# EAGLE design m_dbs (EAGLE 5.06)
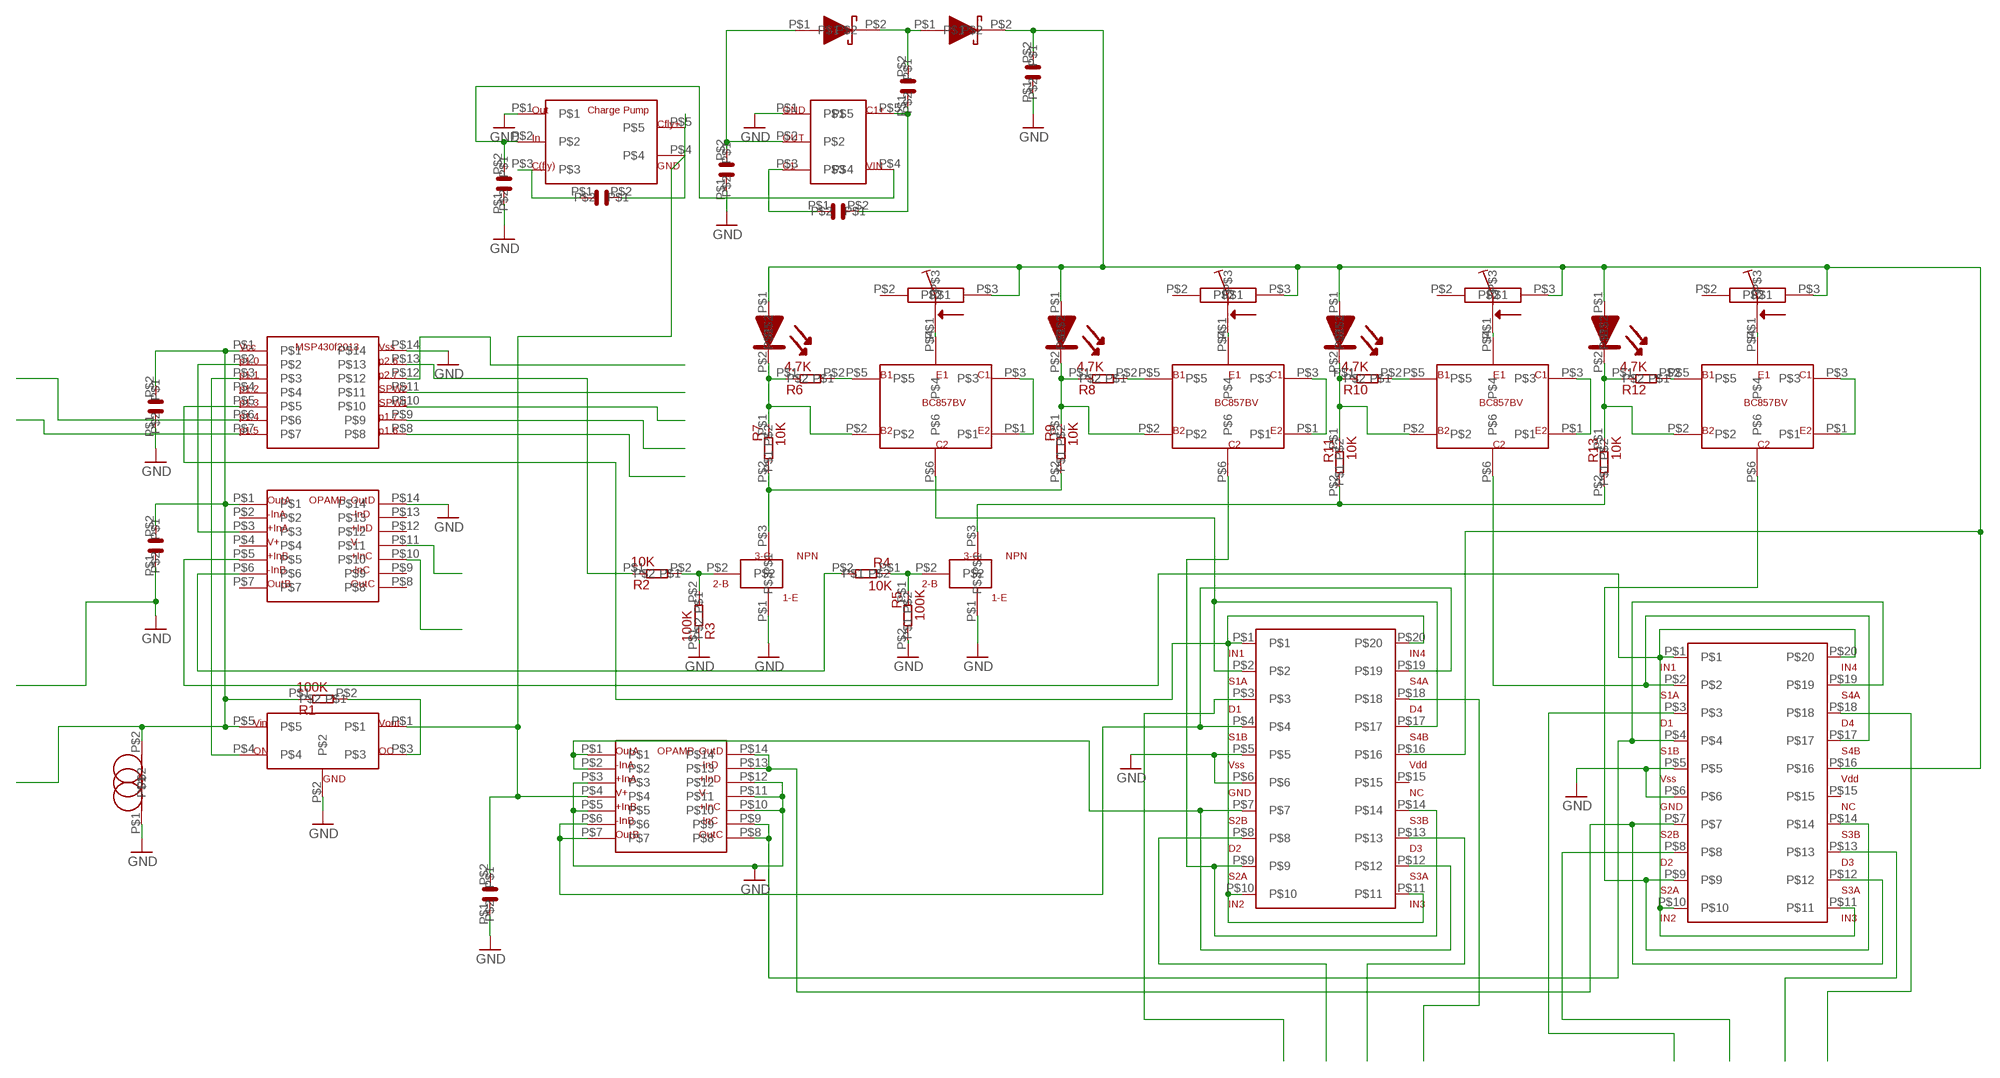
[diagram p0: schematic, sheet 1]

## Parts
C1  1uF  CAP0402  [0402]
C2  1uF  CAP0402  [0402]
C3  1uF  CAP0402  [0402]
C4  10uF  IND0603  [0603]
C5  1uF  CAP0402  [0402]
C6  1uF  CAP0402  [0402]
C7  1uF  CAP0402  [0402]
C8  1uF  CAP0402  [0402]
C9  1uF  CAP0402  [0402]
C10  1uF  CAP0402  [0402]
CP1  CHARGEPUMP  [SOT-23]
CP2  MAX1683  [SOT-23]
D1  DIODE  [SOD923-MC]
D2  DIODE  [SOD923-MC]
LED1  LED  [0402]
LED2  LED  [0402]
LED3  LED  [0402]
LED4  LED  [0402]
MCU1  MSP430F2013  [TSSOP-14]
MCU2  OPAMP  [TSSOP-14]
NPN1  NPN  [SOT-523]
NPN2  NPN  [SOT-523]
OPAMP  OPAMP  [TSSOP-14]
PNP1  BC857BV  [SOT-666]
PNP2  BC857BV  [SOT-666]
PNP3  BC857BV  [SOT-666]
PNP4  BC857BV  [SOT-666]
R1  100K  RES0402  [0402]
R2  10K  RES0402  [0402]
R3  100K  RES0402  [0402]
R4  10K  RES0402  [0402]
R5  100K  RES0402  [0402]
R6  4.7K  RES0402  [0402]
R7  10K  RES0402  [0402]
R8  4.7K  RES0402  [0402]
R9  10K  RES0402  [0402]
R10  4.7K  RES0402  [0402]
R11  10K  RES0402  [0402]
R12  4.7K  RES0402  [0402]
R13  10K  RES0402  [0402]
SPDT1  ADG333  [SSOP-20]
SPDT2  ADG333  [SSOP-20]
SWITCH  SWITCH  [SC70-5]
T1  50K  TRIMMER2MM  [TRIM-MC]
T2  50K  TRIMMER2MM  [TRIM-MC]
T3  50K  TRIMMER2MM  [TRIM-MC]
T4  50K  TRIMMER2MM  [TRIM-MC]

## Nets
GND: C1.P$1 C2.P$1 C3.P$1 C4.P$1 C5.P$1 C7.P$1 C10.P$1 CP1.P$1 CP2.P$1 MCU1.P$14 MCU2.P$14 NPN1.P$1 NPN2.P$1 OPAMP.P$3 OPAMP.P$5 OPAMP.P$10 OPAMP.P$11 OPAMP.P$12 R3.P$1 R5.P$2 SPDT1.P$5 SPDT1.P$6 SPDT2.P$5 SPDT2.P$6 SWITCH.P$2
N$1: LED1.P$2 PNP1.P$2 R6.P$1 R7.P$1
N$2: PNP1.P$5 R6.P$2
N$3: LED2.P$2 PNP2.P$2 R8.P$1 R9.P$1
N$4: PNP2.P$5 R8.P$2
N$5: LED3.P$2 PNP3.P$2 R10.P$1 R11.P$1
N$6: PNP3.P$5 R10.P$2
N$7: LED4.P$2 PNP4.P$2 R12.P$1 R13.P$1
N$8: PNP4.P$5 R12.P$2
N$9: PNP1.P$4 T1.P$1
N$10: PNP2.P$4 T2.P$1
N$11: PNP3.P$4 T3.P$1
N$12: PNP4.P$4 T4.P$1
N$13: OPAMP.P$1 OPAMP.P$2 SPDT1.P$7 SPDT1.P$12
N$14: NPN1.P$3 R7.P$2 R9.P$2
N$15: NPN2.P$2 R4.P$1 R5.P$1
N$16: MCU2.P$6 R4.P$2
N$17: MCU1.P$2 MCU2.P$3
N$18: PNP1.P$1 PNP1.P$3
N$19: PNP2.P$1 PNP2.P$3
N$20: PNP3.P$1 PNP3.P$3
N$21: PNP4.P$1 PNP4.P$3
N$22: NPN1.P$2 R2.P$2 R3.P$2
N$23: MCU1.P$13 R2.P$1
N$24: NPN2.P$3 R11.P$2 R13.P$2
N$25: MCU1.P$3 SWITCH.P$4
N$26: R1.P$2 SWITCH.P$3
N$27: C1.P$2 C2.P$2 C4.P$2 MCU1.P$1 MCU2.P$1 R1.P$1 SWITCH.P$5
N$28: MCU1.P$5 SPDT1.P$1 SPDT1.P$10 SPDT1.P$11 SPDT1.P$20
N$29: MCU2.P$5 SPDT2.P$1 SPDT2.P$10 SPDT2.P$11 SPDT2.P$20
N$30: C3.P$2 CP1.P$4 OPAMP.P$4 SWITCH.P$1
N$33: OPAMP.P$8 OPAMP.P$9 SPDT2.P$4 SPDT2.P$19
N$34: OPAMP.P$13 OPAMP.P$14 SPDT2.P$7 SPDT2.P$12
N$35: C8.P$1 CP2.P$3
N$36: C6.P$1 CP1.P$3
N$37: C6.P$2 CP1.P$5
N$38: C5.P$2 CP1.P$2 CP2.P$4
N$39: C8.P$2 C9.P$1 CP2.P$5
N$40: C9.P$2 D1.P$2 D2.P$1
N$41: C10.P$2 D2.P$2 LED1.P$1 LED2.P$1 LED3.P$1 LED4.P$1 SPDT1.P$16 SPDT2.P$16 T1.P$3 T2.P$3 T3.P$3 T4.P$3
N$42: C7.P$2 CP2.P$2 D1.P$1
N$43: OPAMP.P$6 OPAMP.P$7 SPDT1.P$4 SPDT1.P$19
N$44: PNP1.P$6 SPDT1.P$2 SPDT1.P$17
N$51: PNP3.P$6 SPDT2.P$2 SPDT2.P$17
N$53: PNP4.P$6 SPDT2.P$9 SPDT2.P$14
N$59: MCU1.P$6
N$60: PNP2.P$6 SPDT1.P$9 SPDT1.P$14
N$67: MCU1.P$7
N$68: MCU1.P$11
N$69: MCU1.P$10
N$70: MCU1.P$9
N$71: MCU1.P$8
N$72: MCU1.P$12
N$73: SPDT2.P$8
N$74: MCU2.P$11
N$75: MCU2.P$10
N$76: SPDT1.P$3
N$77: SPDT1.P$8
N$78: SPDT1.P$13
N$79: SPDT1.P$18
N$80: SPDT2.P$3
N$81: SPDT2.P$13
N$82: SPDT2.P$18
Unconnected: MCU1.P$4 MCU2.P$2 MCU2.P$4 MCU2.P$7 MCU2.P$8 MCU2.P$9 MCU2.P$12 MCU2.P$13 SPDT1.P$15 SPDT2.P$15 T1.P$2 T2.P$2 T3.P$2 T4.P$2

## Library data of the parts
C1-C3 C5-C10 = my project parts:CAP0402
C4 = my project parts:IND0603
CP1 = my project parts:CHARGEPUMP
CP2 = my project parts:MAX1683
D1 D2 = my project parts:DIODE
LED1-LED4 = my project parts:LED
MCU1 = my project parts:MSP430F2013
MCU2 OPAMP = my project parts:OPAMP
NPN1 NPN2 = my project parts:NPN
PNP1-PNP4 = my project parts:BC857BV
R1-R13 = my project parts:RES0402
SPDT1 SPDT2 = my project parts:ADG333
SWITCH = my project parts:SWITCH
T1-T4 = my project parts:TRIMMER2MM

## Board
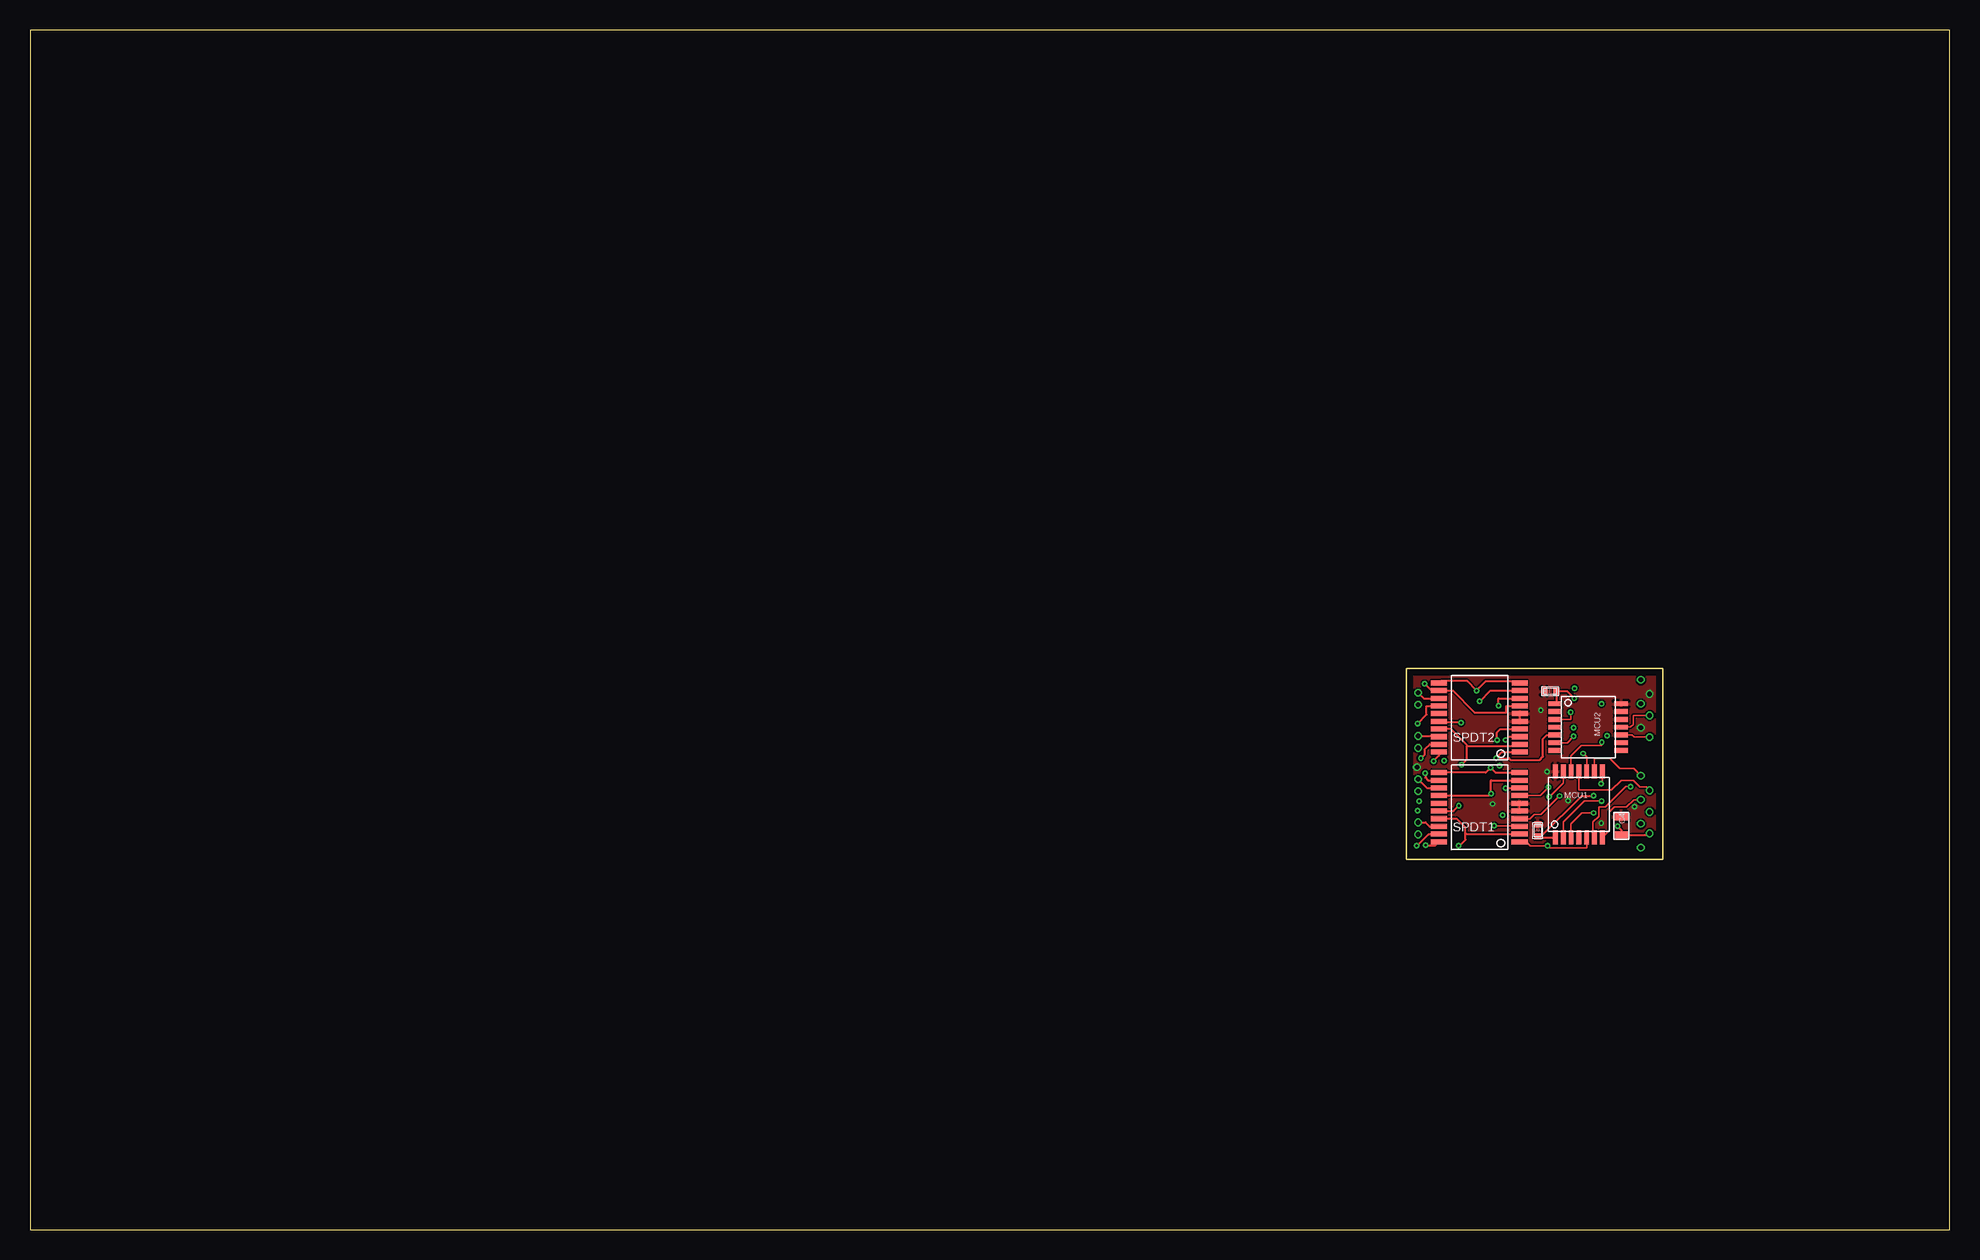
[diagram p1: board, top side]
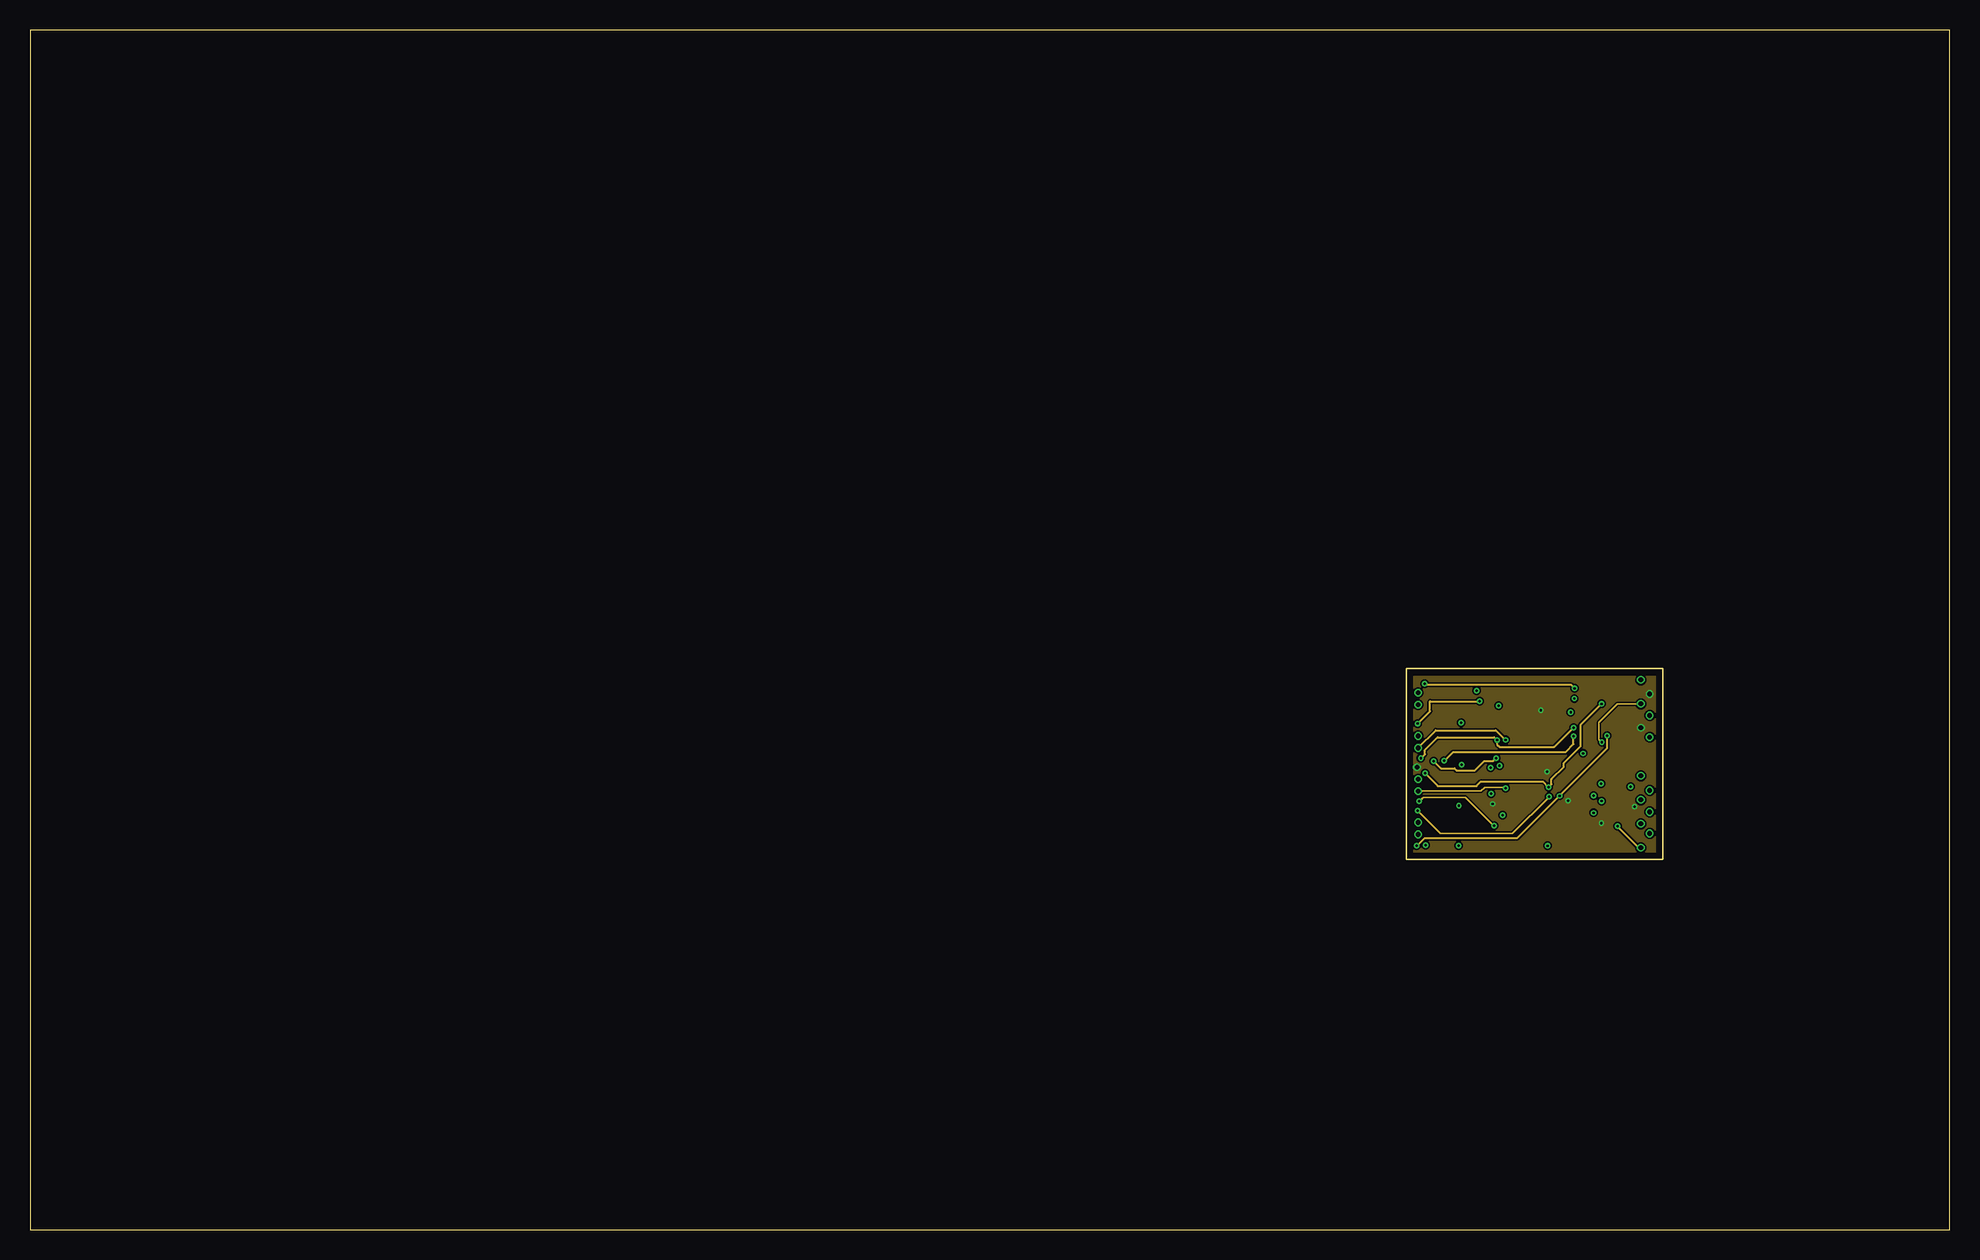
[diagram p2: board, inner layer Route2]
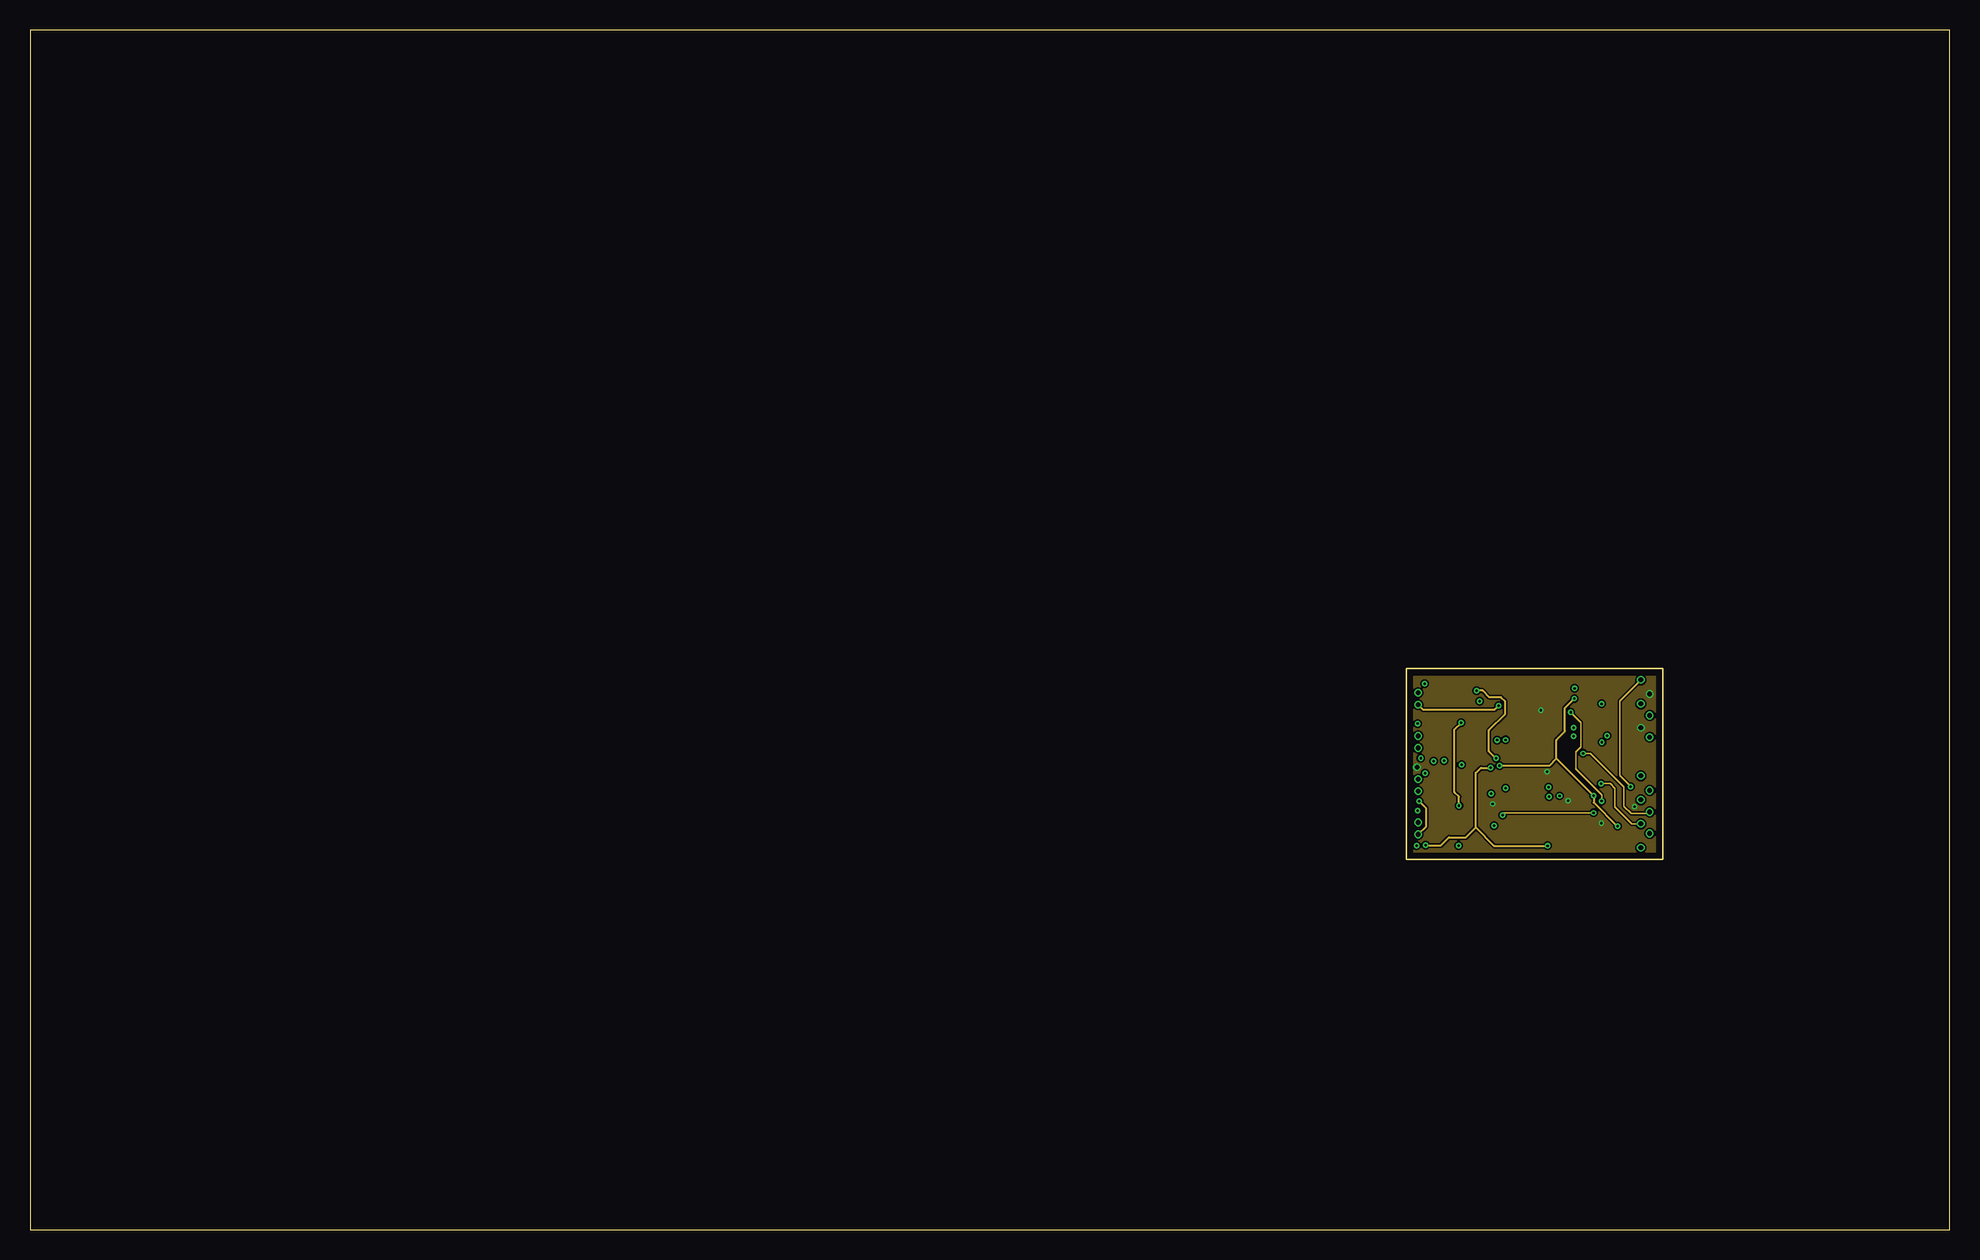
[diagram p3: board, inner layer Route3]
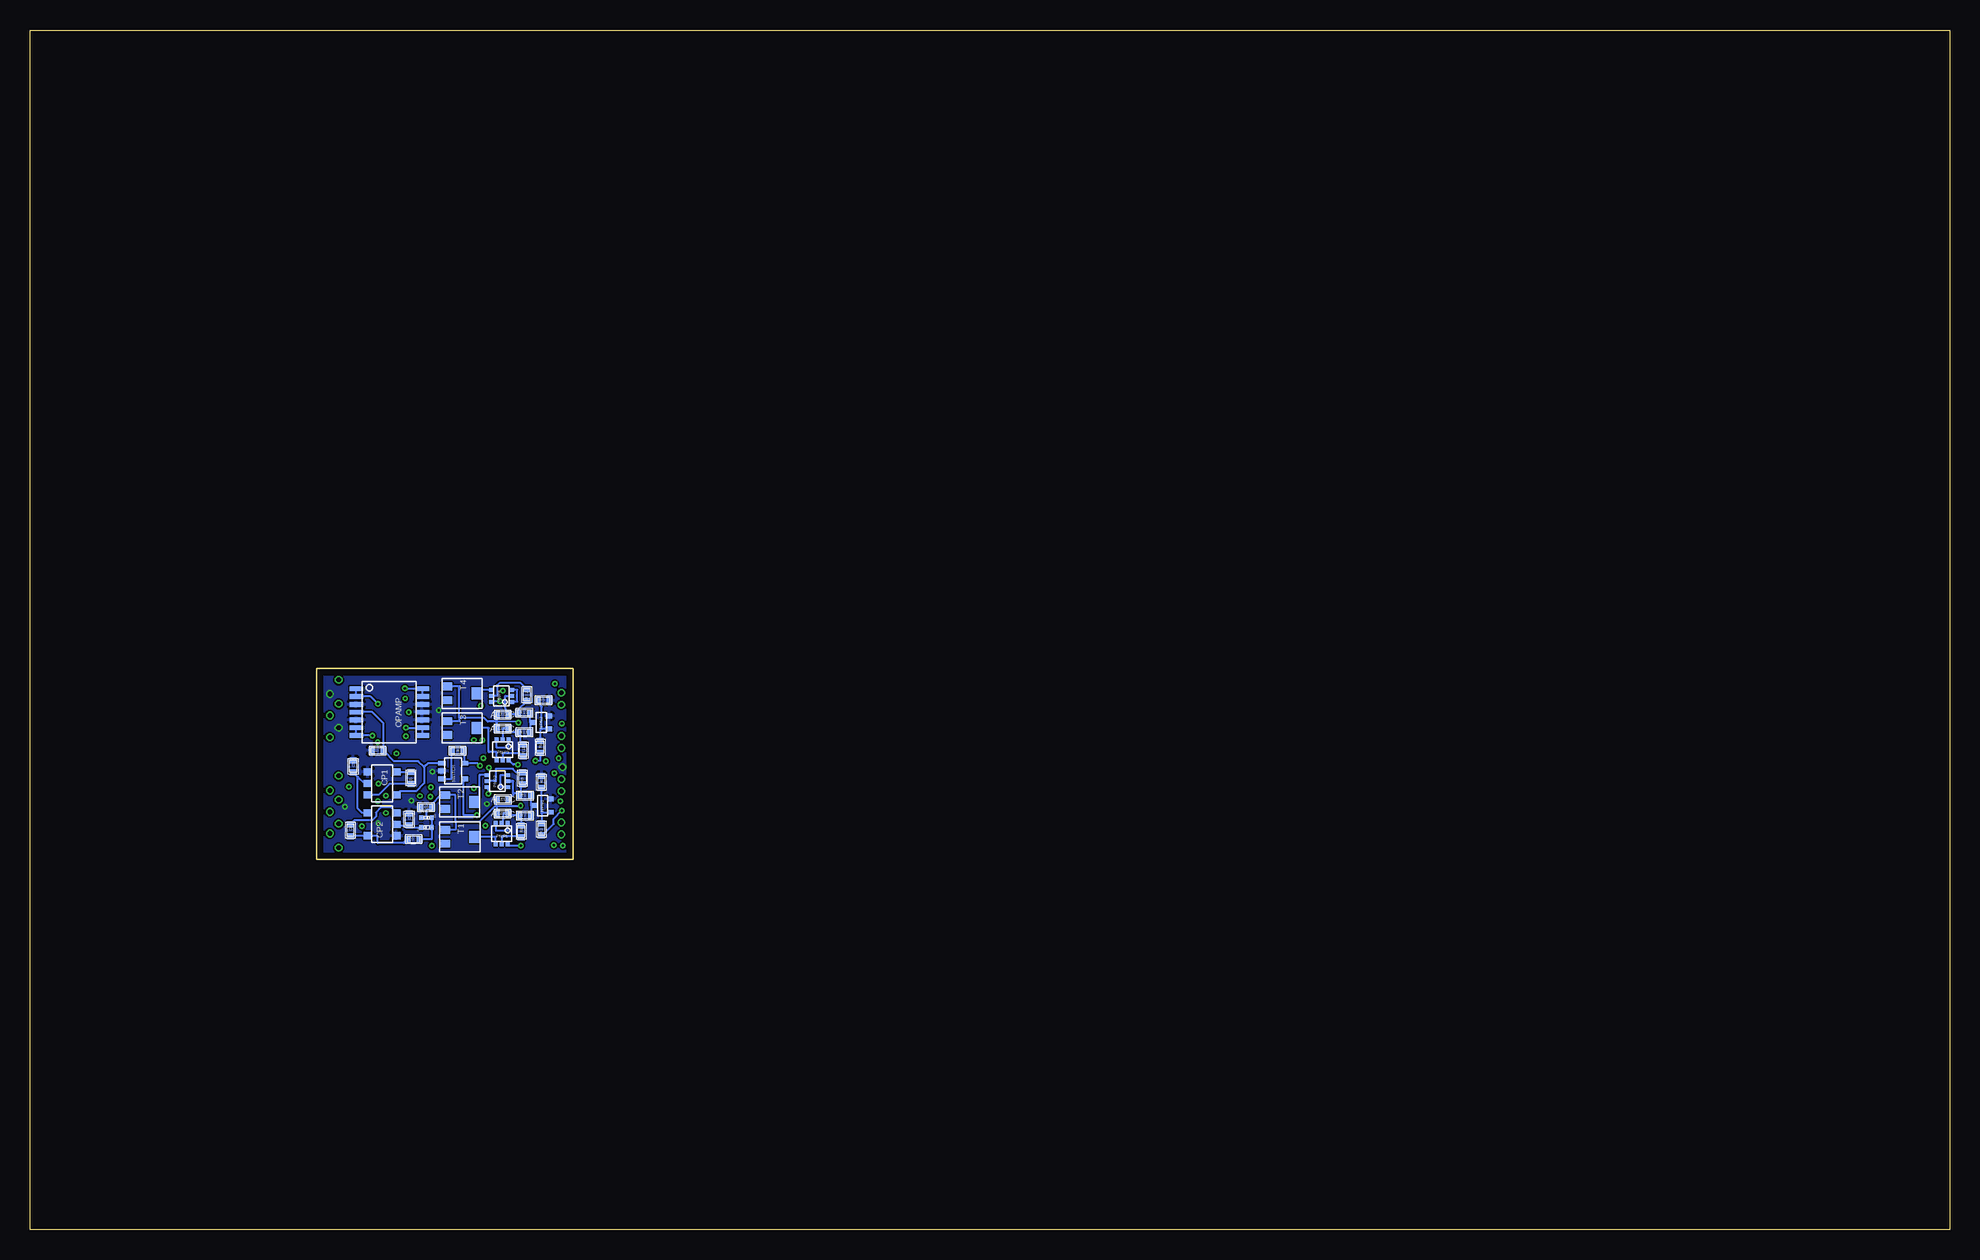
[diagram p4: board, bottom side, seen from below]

Size 160 x 100 mm. Coordinates in mm from the lower left corner, seen from the top.
Outline: 0,0 160,0 160,100 0,100 0,0
Outline: 114.72,46.78 136.1,46.78 136.1,30.85 114.72,30.85 114.72,46.78
Copper layers (1+2*3+16): Top 0.035mm / dielectric 0.38mm / Route2 0.035mm / dielectric 0.71mm / Route3 0.035mm / dielectric 0.38mm / Bottom 0.035mm
Design rules "default *": minimum track width 0.125mm, minimum drill 0.2mm, track to track 5mil, track to pad 6mil, pad to pad 6mil, via to via 5mil, smd to smd 6mil, copper to edge 0.5mm, drill to drill 8mil, minimum pad ring 10mil, minimum via ring 5mil, stop-mask expansion 3mil, vias tented up to drill 8mil, thermal gap 0.2mm

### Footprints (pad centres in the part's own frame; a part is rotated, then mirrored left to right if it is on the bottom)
0402 = smd 0.5 x 0.6: P$1 -0.5,0; P$2 0.5,0
0603 = smd 0.629 x 1.138: P$1 -0.764,0; P$2 0.764,0
SOT-23 = smd 0.6 x 0.725: P$1 -0.95,-1.188; P$2 0,-1.188; P$3 0.95,-1.188; P$4 0.95,1.188; P$5 -0.95,1.188
SOD923-MC = smd 0.3 x 0.4: P$1 -0.45,0; P$2 0.45,0
TSSOP-14 = smd 0.4 x 1.15: P$1 -1.95,-2.75; P$2 -1.3,-2.75; P$3 -0.65,-2.75; P$4 0,-2.75; P$5 0.65,-2.75; P$6 1.3,-2.75; P$7 1.95,-2.75; P$8 1.95,2.75; P$9 1.3,2.75; P$10 0.65,2.75; P$11 0,2.75; P$12 -0.65,2.75; P$13 -1.3,2.75; P$14 -1.95,2.75
SOT-523 = smd 0.4 x 0.55: P$1 0.55,-0.65; P$2 -0.55,-0.65; P$3 0,0.65
SOT-666 = smd 0.3 x 0.4: P$1 -0.5,-0.85; P$2 0,-0.85; P$3 0.5,-0.85; P$4 0.5,0.85; P$5 0,0.85; P$6 -0.5,0.85
SSOP-20 = smd 0.42 x 1.34: P$1 -2.88,-3.36; P$2 -2.24,-3.36; P$3 -1.6,-3.36; P$4 -0.96,-3.36; P$5 -0.32,-3.36; P$6 0.32,-3.36; P$7 0.96,-3.36; P$8 1.6,-3.36; P$9 2.24,-3.36; P$10 2.88,-3.36; P$11 2.88,3.36; P$12 2.24,3.36; P$13 1.6,3.36; P$14 0.96,3.36; P$15 0.32,3.36; P$16 -0.32,3.36; P$17 -0.96,3.36; P$18 -1.6,3.36; P$19 -2.24,3.36; P$20 -2.88,3.36
SC70-5 = smd 0.4 x 0.6: P$1 -0.65,-0.95; P$2 0,-0.95; P$3 0.65,-0.95; P$4 0.65,0.95; P$5 -0.65,0.95
TRIM-MC = smd 1 x 0.9: P$1 0,1.25 | smd 0.65 x 0.9: P$2 0.575,-1.25; P$3 -0.575,-1.25

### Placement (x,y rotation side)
C1  126.71,44.87 0 top
C2  125.68,33.25 270 top
C3  131.03,39.92 0 bottom
C4  132.64,33.65 270 top
C5  133.06,38.61 270 bottom
C6  128.24,37.65 90 bottom
C7  128.39,34.2 270 bottom
C8  133.29,33.29 270 bottom
C9  128.02,32.53 0 bottom
C10  127,35.2 0 bottom
CP1  130.65,37.19 270 bottom
CP2  130.65,33.78 90 bottom
D1  126.94,33.52 0 bottom
D2  126.94,34.33 180 bottom
LED1  120.61,34.67 0 bottom
LED2  120.59,35.85 0 bottom
LED3  120.6,41.75 0 bottom
LED4  120.6,42.92 0 bottom
MCU1  129.11,35.45 0 top
MCU2  129.88,41.88 270 top
NPN1  117.27,35.35 90 bottom
NPN2  117.39,42.27 90 bottom
OPAMP  130.04,43.13 270 bottom
PNP1  120.69,33 180 bottom
PNP2  121.04,37.38 90 bottom
PNP3  120.61,39.99 180 bottom
PNP4  120.7,44.48 90 bottom
R1  124.37,39.92 180 bottom
R2  117.37,33.36 90 bottom
R3  117.37,37.3 270 bottom
R4  117.47,40.21 270 bottom
R5  117.2,44.12 0 bottom
R6  119.05,33.18 270 bottom
R7  118.74,34.51 0 bottom
R8  118.94,37.62 90 bottom
R9  118.74,36.18 0 bottom
R10  118.89,39.95 270 bottom
R11  118.8,41.44 0 bottom
R12  118.58,44.57 90 bottom
R13  118.8,43.07 0 bottom
SPDT1  120.81,35.21 90 top
SPDT2  120.81,42.68 90 top
SWITCH  124.72,38.22 270 bottom
T1  124.19,32.74 270 bottom
T2  124.19,35.63 270 bottom
T3  124,41.8 270 bottom
T4  124,44.7 270 bottom

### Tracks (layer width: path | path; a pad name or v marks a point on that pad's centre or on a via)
GND  (via drill 0.2, 0.4)
  Top 0.125: SPDT2.P$6 SPDT2.P$5 | SPDT1.P$6 SPDT1.P$5
  other vias: 130.98,33.86 128.21,35.76 134.28,41.83 135,44.64 125.94,43.28 126.47,38.16 115.62,38.55 133.75,35.26 121.92,35.48
  pour Top: 114.83,46.27 135.74,46.27 135.74,31.24 114.83,31.24 114.83,46.27
  pour Route2: 114.84,46.27 135.75,46.27 135.75,31.18 114.84,31.18 114.84,46.27
  pour Route3: 114.83,46.28 135.75,46.28 135.75,31.21 114.83,31.21 114.83,46.28
  pour Bottom: 114.88,46.22 135.77,46.22 135.77,31.21 114.88,31.21
N$1
  Bottom 0.125: LED1.P$2 120.11,34.51 | R7.P$1 119.05,34.51 119.05,34.5 | R6.P$1 119.05,33.5
  Bottom 0.15: PNP1.P$2 arc-27 120.56,34.37 120.56,34.67 LED1.P$2 119.94,34.51 R7.P$1 | 119.05,34.5 R6.P$1
N$2
  Bottom 0.125: 118.97,32.66 R6.P$2 119.11,32.66
  Bottom 0.15: PNP1.P$5 120.69,32.79 119.05,32.79 R6.P$2
N$3
  Bottom 0.125: R8.P$1 119.15,37.23 | R9.P$1 119.05,36.18 | R9.P$1 119.24,36.11 | PNP2.P$2 arc-90 120.1,37.29 119.72,37.29 | R9.P$1 119.24,36.37
  Bottom 0.15: 119.72,36.37 119.72,36.22 LED2.P$2 | 119.72,36.37 119.43,36.37 R9.P$1 | 119.72,36.37 119.72,37.38 PNP2.P$2 | 119.05,36.18 119.05,37.12 R8.P$1
N$4
  Bottom 0.125: 118.94,37.96 R8.P$2 118.94,38.2
  Bottom 0.15: PNP2.P$5 121.18,37.38 121.18,38.41 119.76,38.41 119.48,38.12 R8.P$2
N$5
  Bottom 0.125: 119.12,41.44 R11.P$1 | R10.P$1 119.12,40.45
  Bottom 0.15: PNP3.P$2 120.59,40.84 120.59,41.75 LED3.P$2 120.1,41.44 R11.P$1 | 119.12,41.44 119.12,40.67 R10.P$1
N$6
  Bottom 0.125: R10.P$2 118.89,39.62
  Bottom 0.15: PNP3.P$5 120.61,39.69 119.13,39.69 R10.P$2
N$7
  Bottom 0.125: 119.11,43.07 R13.P$1 119.3,42.92
  Bottom 0.15: 119.3,42.92 LED4.P$2 120.39,43.48 120.39,44.48 PNP4.P$2 | R12.P$1 119.3,43.35 R13.P$1
N$8
  Bottom 0.15: PNP4.P$5 121.06,44.48 121.06,45.36 120.87,45.55 119.09,45.55 118.61,45.07 R12.P$2
N$9
  Bottom 0.15: PNP1.P$4 121.19,32.74 T1.P$1
N$10
  Bottom 0.125: 122.55,36.02 T2.P$1
  Bottom 0.15: PNP2.P$4 122.55,37.88 122.55,36.02
N$11
  Bottom 0.15: PNP3.P$4 121.11,39.79 121.77,39.79 121.77,41.8 T3.P$1
N$12
  Bottom 0.125: PNP4.P$4 121.94,44.98
  Bottom 0.15: T4.P$1 122.75,44.98 PNP4.P$4
N$13  (via drill 0.2)
  Top 0.125: SPDT1.P$12 | v126.58,36.87 125.88,36.17 SPDT1.P$7
  Top 0.15: SPDT1.P$12 116.54,37.45 116.31,37.68 v116.31,38.05
  Route2 0.125: v116.31,38.05 116.31,38.01
  Route2 0.15: 116.31,38.01 117.35,36.96 120.56,36.96 120.95,37.35 126.1,37.35 v126.58,36.87 126.83,37.12 126.83,37.56 127.85,38.58 127.85,38.88 129.27,40.3 129.27,42.1 v130.98,43.81
  Bottom 0.15: OPAMP.P$1 OPAMP.P$2 131.6,44.43 v130.98,43.81
N$14
  Bottom 0.15: R9.P$2 118.24,35.35 NPN1.P$3 118.24,35.35 R7.P$2
N$15
  Bottom 0.125: 117.48,41.72 117.47,41.72 117.34,41.72
  Bottom 0.15: R4.P$1 117.47,41.72 NPN2.P$2 | 117.34,41.72 117.34,43.56 R5.P$1
N$16  (via drill 0.2)
  Top 0.125: MCU2.P$6 128.13,40.58 v128.66,41.12
  Route2 0.15: v117.89,39.07 118.63,39.81 128.01,39.81 128.66,40.47 v128.66,41.12
  Bottom 0.15: v117.89,39.07 117.47,39.07 R4.P$2
N$17  (via drill 0.2)
  Top 0.125: v131,35.73 129.54,35.73 127.81,33.99 MCU1.P$2 | MCU2.P$3 128.43,42.53 v128.43,43.11
  Route3 0.125: v131,35.73 131,36.24 128.86,38.39 128.86,39.82 129.26,40.22 129.26,42.29 v128.43,43.11
N$18
  Bottom 0.15: PNP1.P$1 120.19,33.25 121.19,33.25 PNP1.P$3
N$19
  Bottom 0.15: PNP2.P$3 120.78,37.88 120.78,36.88 PNP2.P$1
N$20
  Bottom 0.15: PNP3.P$1 120.11,40.2 121.11,40.2 PNP3.P$3
N$21
  Bottom 0.15: PNP4.P$3 119.38,44.98 119.38,43.98 PNP4.P$1
N$22
  Bottom 0.125: R3.P$2
  Bottom 0.15: 117.37,34.73 R2.P$2 | 117.37,34.73 R3.P$2 | NPN1.P$2 116.69,34.73 117.37,34.73
N$23  (via drill 0.2)
  Top 0.125: MCU1.P$13 127.81,37.24 v126.64,36.08
  Route2 0.125: v126.64,36.08 123.57,33 117.58,33 v115.66,34.92
  Bottom 0.15: R2.P$1 117.29,32.86 116.34,33.81 116.34,34.25 115.67,34.92 v115.66,34.92
N$24
  Bottom 0.125: 118.3,42.27 NPN2.P$3 118.3,42.27
  Bottom 0.15: 118.3,42.27 R11.P$2 | 118.3,42.27 R13.P$2
N$25  (via drill 0.2)
  Top 0.125: v130.35,34.73 129.37,34.73 128.46,33.82 MCU1.P$3
  Route3 0.125: v122.74,34.53 122.74,34.73 v130.35,34.73
  Bottom 0.125: 123.84,37.57 SWITCH.P$4 | 123.84,34.53
  Bottom 0.15: 123.84,37.57 123.84,34.53 v122.74,34.53
N$26
  Bottom 0.125: R1.P$2 124.95,39.84
  Bottom 0.15: SWITCH.P$3 124.87,37.57 R1.P$2
N$27  (via drill 0.2, 0.4)
  Top 0.125: 127.21,43.91 MCU2.P$1 | 125.74,32.7 C2.P$2 125.88,32.75 | C4.P$2 132.92,32.88
  Top 0.15: v128.73,44.27 128.13,44.87 C1.P$2 127.21,43.91 | v130.34,36.15 129.35,36.15 125.95,32.75 C2.P$2 | 125.74,32.7 MCU1.P$1 | v132.32,33.62 132.64,33.3 C4.P$2 134.87,32.88 v135,33.02
  Route2 0.15: v132.32,33.62 134.11,31.83 v134.28,31.83
  Route3 0.125: v132.32,33.62
  Route3 0.15: v128.73,44.27 127.96,43.5 127.96,41.53 127.24,40.81 127.24,39.25 | 127.24,39.25 126.64,38.66 v122.48,38.66 | 127.24,39.25 v130.34,36.15 130.34,35.6 v132.32,33.62
  Bottom 0.125: 123.77,39.81 R1.P$1
  Bottom 0.15: 123.77,39.81 SWITCH.P$5 122.7,38.87 v122.48,38.66
N$28  (via drill 0.2)
  Top 0.125: SPDT1.P$1 124.23,32.26 124.77,32.26 125.05,31.98 v126.5,31.98 126.69,31.8 129.76,31.8 MCU1.P$5
  Top 0.15: SPDT1.P$10 122.16,38.09 v121.75,38.5 121.35,38.09 SPDT1.P$11 | SPDT1.P$20 117.15,32.04 v116.34,32.04
  Route3 0.15: v116.34,32.04 117.62,32.04 118.29,32.7 119.7,32.7 120.5,33.5 | 120.5,33.5 122.03,31.98 v126.5,31.98 | 120.5,33.5 120.5,38.06 120.94,38.5 v121.75,38.5
N$29  (via drill 0.2)
  Top 0.125: 124.02,45.71 SPDT2.P$10 | 117.6,45.71 SPDT2.P$11
  Top 0.15: 124.02,45.71 121.36,45.71 v120.58,44.93 119.8,45.71 117.6,45.71 | v117,39.06 117.45,39.51 SPDT2.P$20 | SPDT2.P$1 122.71,39.8 v122.19,39.29 123.29,39.29 123.43,39.15 125.84,39.15 126.11,39.43 126.11,40.91 126.43,41.23 MCU2.P$5
  Route2 0.15: v117,39.06 117.62,38.44 118.74,38.44 118.9,38.28 120.45,38.28 121.22,39.05 121.95,39.05 v122.19,39.29
  Route3 0.15: v120.58,44.93 121.09,44.93 121.66,44.36 122.61,44.36 122.96,44.01 122.96,42.98 121.62,41.64 121.62,39.87 v122.19,39.29
N$30
  Bottom 0.125: 127.13,38.54 127.15,38.54
  Bottom 0.15: OPAMP.P$4 131.47,43.13 130.53,42.19 C3.P$2 129.64,39.03 127.64,39.03 127.15,38.54 | SWITCH.P$1 126.81,38.87 127.13,38.54 127.13,37.22 127.81,36.54 129.17,36.54 CP1.P$4
N$33  (via drill 0.2)
  Top 0.15: SPDT2.P$19 116.67,40.44 116.27,40.04 116.27,39.62 v115.94,39.29 | SPDT2.P$4 122.58,41.72 122.29,41.43 v122.29,40.81
  Route2 0.15: v115.94,39.29 116.27,39.62 116.27,39.98 117.33,41.04 122.06,41.04 v122.29,40.81 122.29,40.45 122.5,40.23 127.06,40.23 v128.66,41.83
  Bottom 0.15: OPAMP.P$8 OPAMP.P$9 v128.66,41.83
N$34  (via drill 0.2)
  Top 0.125: 116.82,44.92 SPDT2.P$12
  Top 0.15: SPDT2.P$7 123.05,43.64 123.05,43.09 120.42,43.09 118.59,44.92 SPDT2.P$12 | v116.25,45.49 116.82,44.92
  Route2 0.15: v116.25,45.49 116.31,45.43 128.43,45.43 v128.75,45.11
  Bottom 0.15: v128.75,45.11 127.32,45.11 OPAMP.P$14 OPAMP.P$13
N$35
  Bottom 0.15: CP2.P$3 129.9,35.17 130.75,35.17 131.15,34.77 131.15,34.42 131.46,34.11 132.97,34.11 C8.P$1
N$36
  Bottom 0.125: CP1.P$3 131.42,36.24 | C6.P$1 arc-90 C6.P$1
  Bottom 0.15: C6.P$1 130.03,37.16 130.95,36.24 CP1.P$3
N$37
  Bottom 0.125: C6.P$2
  Bottom 0.15: CP1.P$5 C6.P$2
N$38
  Bottom 0.125: CP1.P$2 131.84,37.13 132.08,37.13
  Bottom 0.15: 132.69,37.73 132.08,37.13 | 132.69,37.73 C5.P$2 | 132.69,37.73 132.69,35.09 132.33,34.73 CP2.P$4
N$39
  Bottom 0.125: 131.84,32.8 CP2.P$5 | C9.P$1 128.52,32.29
  Bottom 0.15: C8.P$2 131.84,32.8 131.01,32.8 131.01,32.22 128.83,32.22 C9.P$1
N$40
  Bottom 0.125: D2.P$1
  Bottom 0.15: C9.P$2 126.49,32.53 D1.P$2 D2.P$1
N$41  (via drill 0.2)
  Top 0.125: 117.56,42.25 SPDT2.P$16
  Top 0.15: v119.29,42.25 117.56,42.25 | SPDT1.P$16 118.66,34.89 v119.11,35.34
  Route3 0.125: 119.29,42.24 v119.29,42.25
  Route3 0.15: 119.29,42.24 118.75,41.69 118.75,36.45 119.11,36.09 v119.11,35.34
  Bottom 0.125: LED1.P$1 120.98,34.61 | LED1.P$1 121.11,34.74 | LED1.P$1 | LED4.P$1 121.1,42.34 119.38,42.34 v119.29,42.25 | 121.09,35.25 121.09,34.69 LED1.P$1 | T2.P$3 125.78,36.21
  Bottom 0.15: D2.P$2 126.99,34.33 126.99,34.98 126.5,34.98 C10.P$2 126.5,35.49 125.78,36.21 | T1.P$3 124.53,33.32 124.53,33.98 | T2.P$3 124.53,36.21 124.53,33.98 | 124.53,33.98 122.55,33.98 121.28,35.25 121.09,35.25 | 121.09,35.25 LED2.P$1 | 121.09,35.25 121.09,34.76 | 121.09,35.25 119.19,35.25 v119.11,35.34 | 124.22,42.63 122.13,42.63 121.84,42.34 121.1,42.34 LED3.P$1 | T3.P$3 124.22,42.37 124.22,42.63 | T4.P$3 124.22,45.27 124.22,42.63 | 121.1,42.99 121.1,41.64 LED4.P$1
N$42
  Bottom 0.125: CP2.P$2 129.46,33.7 | C7.P$2 128.39,33.52
  Bottom 0.15: 129.46,33.7 C7.P$2 128.21,33.52 D1.P$1
N$43  (via drill 0.2)
  Top 0.125: v115.6,32.01 115.6,32.11 115.76,32.11 | v127.49,36.15 125.95,34.6 125.39,34.6 125.04,34.25 SPDT1.P$4
  Top 0.15: SPDT1.P$19 116.6,32.97 115.65,32.01 v115.6,32.01
  Route2 0.125: v127.49,36.14 v127.49,36.15
  Route2 0.15: v131.47,41.17 131.47,40.13 v127.49,36.15 | v127.49,36.14 123.98,32.63 116.26,32.63 115.65,32.01 v115.6,32.01
  Bottom 0.15: OPAMP.P$6 OPAMP.P$7 131.48,41.18 v131.47,41.17
N$44  (via drill 0.2)
  Top 0.125: SPDT1.P$2 124.1,33.03
  Top 0.15: SPDT1.P$17 118.93,34.25 119.66,33.52 119.66,33.03 | 119.66,33.03 119.66,32.48 119.17,31.99 v119.1,31.99 | 119.66,33.03 119.72,32.97 SPDT1.P$2
  Bottom 0.15: v119.1,31.99 120.02,31.99 PNP1.P$6
N$51  (via drill 0.2)
  Top 0.125: 119.77,40.3 119.77,40.41 | 124.03,40.3 SPDT2.P$2
  Top 0.15: 124.03,40.3 119.77,40.3 119.77,39.17 v119.35,38.76 | SPDT2.P$17 118.45,41.72 119.77,40.41
  Bottom 0.15: PNP3.P$6 119.73,38.76 v119.35,38.76
N$53  (via drill 0.2)
  Top 0.125: SPDT2.P$14
  Top 0.15: v120.84,44.04 121.73,44.92 SPDT2.P$9 | SPDT2.P$14 116.4,43.64 116.4,42.92 v115.67,42.19
  Route2 0.15: v120.84,44.04 116.69,44.04 116.69,43.21 v115.67,42.19
  Bottom 0.125: 121.52,44.04 PNP4.P$6
  Bottom 0.15: v120.84,44.04 121.52,44.04
N$59  (via drill 0.2, 0.4)
  Top 0.125: MCU1.P$6 130.28,32.7 130.28,33.98 130.78,34.43 130.78,35.22 131.31,35.22 133.01,36.92 v133.43,36.92
  Route3 0.125: v133.43,36.92 132.51,37.84 132.51,44.05 v134.28,45.83
N$60  (via drill 0.2)
  Top 0.15: SPDT1.P$14 121.62,36.17 v121.79,36.34 121.79,37.45 SPDT1.P$9
  Bottom 0.125: 121.79,36.88 PNP2.P$6
  Bottom 0.15: v121.79,36.34 121.79,36.88
N$67  (via drill 0.4)
  Top 0.125: 131.06,32.99 MCU1.P$7 131.63,33.27 131.63,34.79 132.04,35.21 133.06,35.21 133.67,35.83 v134.28,35.83
N$68  (via drill 0.4)
  Top 0.125: MCU1.P$11 129.11,36.64 131.82,36.64 132.64,37.46 133.65,37.46 134.21,36.9 134.72,36.9 v135,36.62
N$69  (via drill 0.2, 0.4)
  Top 0.125: MCU1.P$10 129.76,39.4 v129.47,39.69
  Route3 0.125: 129.93,39.69 v129.47,39.69 130.07,39.69 132.87,36.88 132.87,35.27 133.47,34.67 134.86,34.67 v135,34.82
N$70  (via drill 0.4)
  Top 0.125: MCU1.P$9 130.41,39.26 131.7,39.26 132.54,38.42 133.68,38.42 v134.28,37.83
N$71  (via drill 0.2, 0.4)
  Top 0.125: v130.97,37.17 131.06,37.26 MCU1.P$8
  Route3 0.125: v130.97,37.17 131.72,37.17 132.12,36.76 132.12,35.22 133.52,33.83 v134.28,33.83
N$72  (via drill 0.2, 0.4)
  Top 0.125: MCU1.P$12 128.46,39.48 129.33,40.36 131.02,40.36 v131.02,40.62
  Route2 0.125: v131.02,40.62 130.77,40.87 130.77,42.27 132.33,43.83 v134.28,43.83
N$73  (via drill 0.2, 0.4)
  Top 0.15: SPDT2.P$8 122.4,44.28 v122.4,43.66
  Route3 0.15: v115.71,43.75 116.09,43.36 122.1,43.36 v122.4,43.66
N$74  (via drill 0.4)
  Top 0.125: MCU2.P$11 133.42,41.88 133.64,42.11 133.64,42.84 v135,42.84
N$75  (via drill 0.4)
  Top 0.125: MCU2.P$10 133.54,41.23 133.73,41.04 v135,41.04
N$76  (via drill 0.2, 0.4)
  Top 0.125: SPDT1.P$3 124.02,33.75 123.93,33.66 v122.03,33.66
  Route2 0.125: 116.02,35.93 v115.79,35.7 116.13,36.04 119.65,36.04 v122.03,33.66
  Route3 0.15: v115.79,35.7 116.38,35.12 116.38,33.62 v115.71,32.95
N$77  (via drill 0.2, 0.4)
  Top 0.125: v123.01,36.8 v123.02,36.81
  Top 0.15: v123.02,36.81 SPDT1.P$8
  Route2 0.125: v115.71,36.55 120.95,36.55 121.26,36.86 122.96,36.86 v123.01,36.8
N$78  (via drill 0.4)
  Top 0.15: v115.71,37.55 116.44,36.81 SPDT1.P$13
N$79  (via drill 0.4)
  Top 0.15: v115.71,33.95 116.31,33.95 116.65,33.61 SPDT1.P$18
N$80  (via drill 0.2, 0.4)
  Top 0.15: SPDT2.P$3 123.26,41.08 v122.99,40.81
  Route2 0.15: v115.71,40.15 117.18,41.62 122.19,41.62 v122.99,40.81
N$81  (via drill 0.4)
  Top 0.15: v115.71,44.75 116.17,44.28 SPDT2.P$13
N$82  (via drill 0.4)
  Top 0.15: v115.71,41.15 117.39,41.15 SPDT2.P$18

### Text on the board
bNames: C | A | A | C | C | A | C | A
